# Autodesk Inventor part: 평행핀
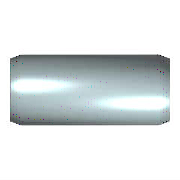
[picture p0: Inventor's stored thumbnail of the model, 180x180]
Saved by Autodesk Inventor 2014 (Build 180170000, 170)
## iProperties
Created: 2009-02
Part Number: 평행핀
Material: 강, 연강
Description: 평행 핀
Document SubType Name: Modeling
Standard: KS B 1320
Designer: KYOUNG IL JANG
Standards Organization: KS
Language: ko-KR
Size Designation: B 5 x  20
Categories: <MemberInstance><Categories><Category DisplayName="조임쇠" InternalName="e4da775c-781d-43d5-af7c-5136215cf5a6" Mnemonic="FSTN"><Category DisplayName="핀" InternalNa
Density: 7.86 g/cm^3
Appearance: 강철
Mass: 3.06605 g
Surface Area: 3.46755 cm^2
Volume: 0.390082 cm^3
IsCustomPart: 0
Author: KYOUNG IL JANG
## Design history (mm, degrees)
sketch "스케치"
  geometry: C1 r 2.5 at (0, 0); 1 further point
  constraints: 1 centre point, 1 coincident
  dimensions: "d1" = 5 diameter of C1 (= NND)
extrude "본체" new body sketch "스케치" distance "d2" = 20 (= NLG); taper "d3" = 0 deg
chamfer "스케치2" distance "d8" = 0.8 (= PHH); stored, may be unused: angle "d9" = 15 deg (= FAWI), second distance "d12" = 0.8 (= PHH)
body "Solid1"
chamfer "모따기1" distance "d4" = 0.8 (= PHH); stored, may be unused: angle "d5" = 15 deg (= FAWI), second distance "d11" = 0.8 (= PHH)
other parameters: "NND" = 5 [user parameter; used in 1 equation term], "NLG" = 20 [user parameter; used in 1 equation term], "PHH" = 0.8 [user parameter; used in 4 equation terms], "FAWI" = 15 deg [user parameter; used in 2 equation terms], "d13" = 0, "d15" = 0, "d16" = 0, "KAH" = 0.63 [user parameter]
